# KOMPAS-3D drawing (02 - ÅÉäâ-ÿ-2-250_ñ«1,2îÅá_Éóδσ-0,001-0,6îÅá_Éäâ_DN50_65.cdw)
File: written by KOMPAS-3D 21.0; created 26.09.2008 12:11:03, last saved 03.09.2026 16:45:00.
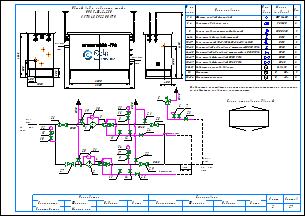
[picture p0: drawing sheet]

Sheets 1-2: A3, landscape

Document properties: Наименование: Макро:21; Автор: RaskoAdmin; Форматы листов документа: 2xA3; Полное имя файла: \\UR38nt01\Departments\КТО\КБ ПУРДГ\Заявки\Прайс-лист на типовые шкафы ГРПШ\ПРДГ_стандарт_20_03_2026\ПРДГ с РДГ(Н, В)\ПРДГ-Ш-2-250_до1,2МПа_Рвых-0,001-0,6МПа_РДГ_DN50_65.cdw

Title block, sheet 1: Наименование: Пункт учета газа / ПУГ-Ш-400-Р / ЛГТИ.485922.001ТУ; designation: ЛГТИ.03.4411141; sheet number: 1; Количество листов документа: 2; organisation: ООО "ЭЛЬСТЕР Газэлектроника"; Форматы листов документа: A3; stored path: C:\Рабочие документы\Компас\ПУГ\Схема.cdw; Разработал: Устинов; Проверил: Кошкин; Утвердил: Кошкин
Title block, sheet 2: sheet number: 2; stored path: D:\Рабочие документы\Заявки\ПУРДГ\ПУРДГ-ШУЭО-2-100-Р 4411220.cdw; designation, second copy: ЛГТИ.03.4411141-

Views: Вид 1, Вид 2
Referenced files: wcvoit.frw
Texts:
  Normal
  № на
  схеме
  Усл.
  обозн.
  Марка
  (модель)
  Кол.
  Фильтр газовый фланцевый
  ФГ 16-50
  Регулятор давления газа
  РДГ-50
  Клапан предохранительный сбросной
  КПС DN20
  Кран шаровой газовый латунный
  DN15
  Кран кнопочный VE-РАСКО-НЗ-1,6-G1/2-М20
  Кран шаровой "под приварку" штуцерный DN20 PN16
  Кран шаровой "под приварку" штуцерный п/п DN20 PN16
  DN20
  Кран шаровой фланцевый DN50 PN16
  Кран шаровой фланцевый DN65 PN16
  DN50
  DN65
  Индикатор перепада давления
  Delta 15
  Манометр
  Манометр-напоромер
  0...     МПа
  0...     кПа
  Общий вид и габариты шкафа
  ПРДГ-Ш-2-250
  Выход газа
  Вход газа
  logo-rasko-ge.png
  Вход
  газа
  PDI
  Выход
  Р=     кПа
  Импульс DN20
  ≥5DN
  HYSWLongFangSong
  Р=       МПа
  Схема открывания дверей
  Предприятие изготовитель может заменять комплектующие на аналогичные,
  не ухудшающие заявленных характеристик.
  Должность
  Конструктор
  Фамилия
  Подпись
  Дата
  Согласовано
  Максимкин
  Лист
  Листов
  POLYLINE_STYLE_0.18_RGB_0_0_0
  POLYLINE_STYLE_0.50_RGB_0_0_0
  POLYLINE_STYLE_0.34_RGB_0_0_0
  PHANTOM_RGB_0_0_0_SC_1_THICK_0.18
  K5LT_THIN_RGB_0_0_0_THICK_0.18
  K5LT32769_RGB_0_0_0_THICK_0.18
  K5LT12_RGB_0_0_0_SC_1_THICK_0.18
  K5LT_DASHED_RGB_0_0_0_SC_1_THICK_0.18
  ACISOTGL_RGB_0_0_0_SC_0.8_THICK_0.25
  CONTINUOUS_RGB_0_127_31_THICK_0.3
  CONTINUOUS_RGB_0_0_255_THICK_0.35
  CONTINUOUS_RGB_255_0_0_THICK_0.35
  POLYLINE_STYLE_0.25_RGB_0_0_0
  CONTINUOUS_RGB_0_0_0_THICK_0.5
  POLYLINE_STYLE_0.35_RGB_0_0_255
  CONTINUOUS_RGB_0_0_0_THICK_0.4
  CONTINUOUS_RGB_0_0_0_THICK_0.35
  Без оформления
Dimensions and other numbers on the sheet: 1; 1, 2; 2; 3, 4; 5; 6-14; 9; 15-17; 3; 18-23; 24-25; 6; 26-27; 28-29; 30-31; 32; 33-34; 400; 1050; 500; 305; 1565; 2800; 1000; 4130; 2500; 4; 10; 27; 28; 29; 23; 8; 12; 19; 20; 21; 22; 25; 24; 30; 31; 15; 16; 26; 7; 11; 14; 13; 33; 17; 34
